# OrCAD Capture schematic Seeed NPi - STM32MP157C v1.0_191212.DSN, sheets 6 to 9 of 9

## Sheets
6 04 USB HOST/Device: size A3
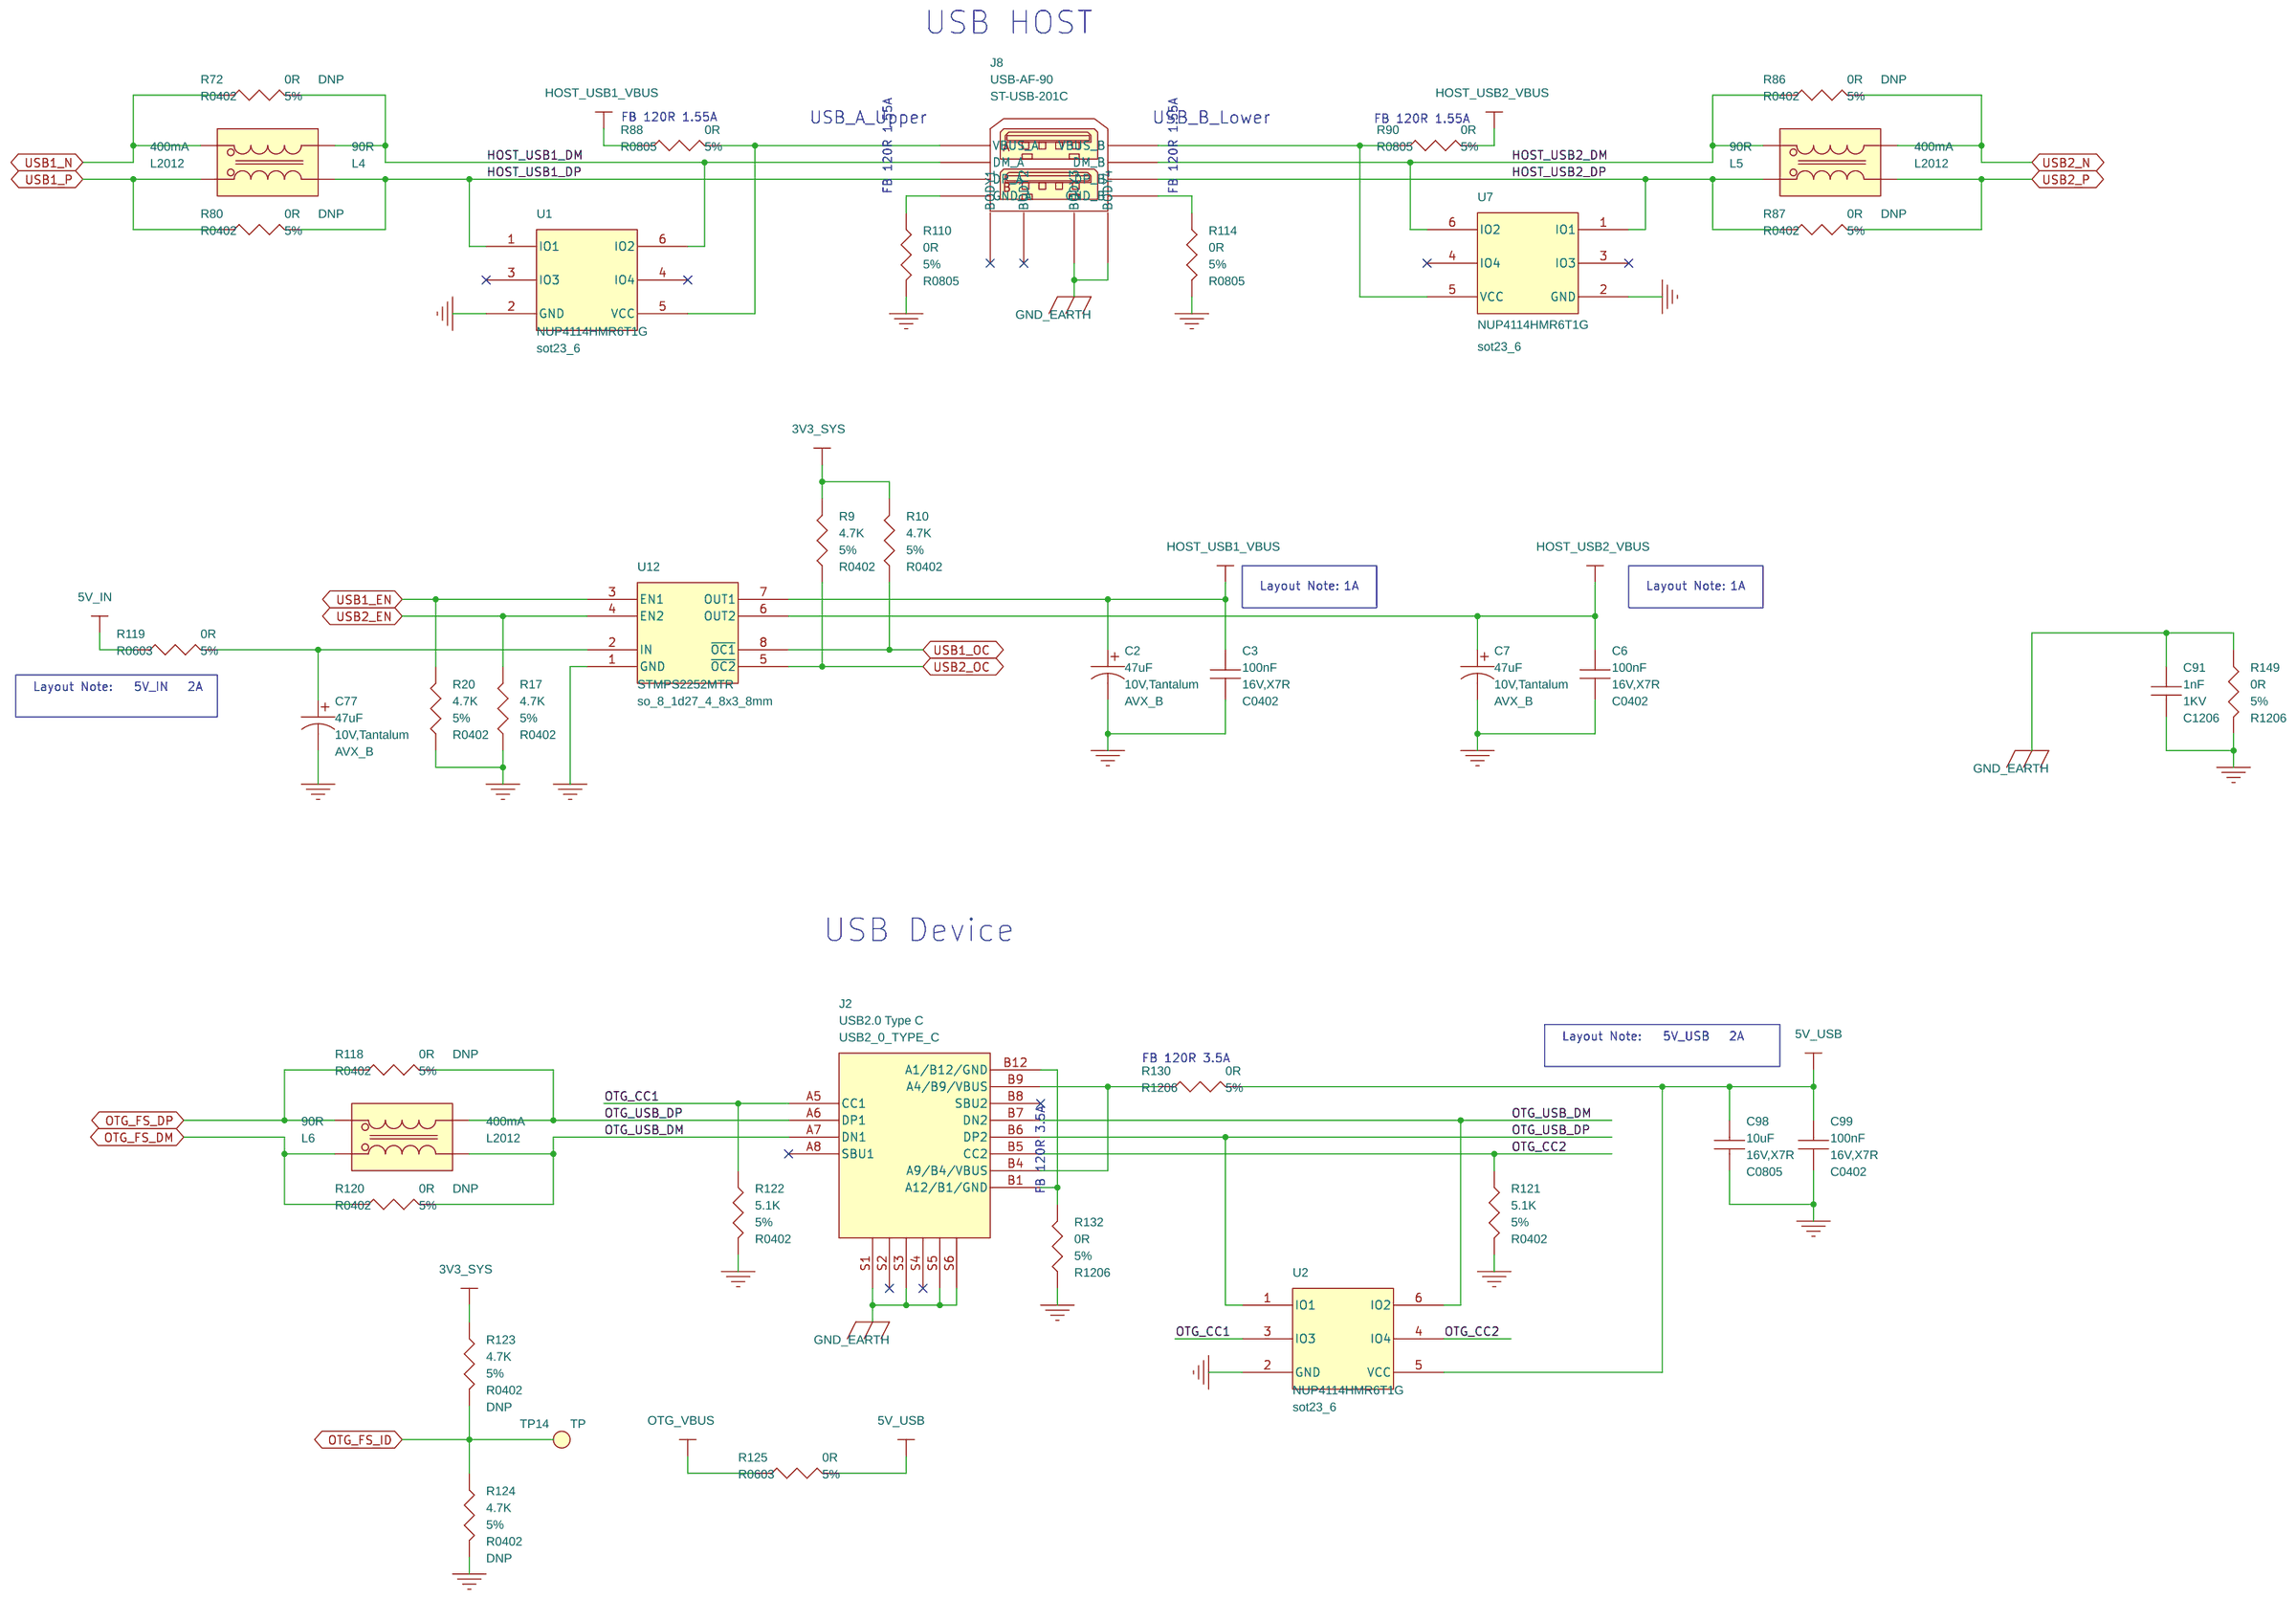
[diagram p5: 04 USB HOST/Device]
7 01 Title / Revision History
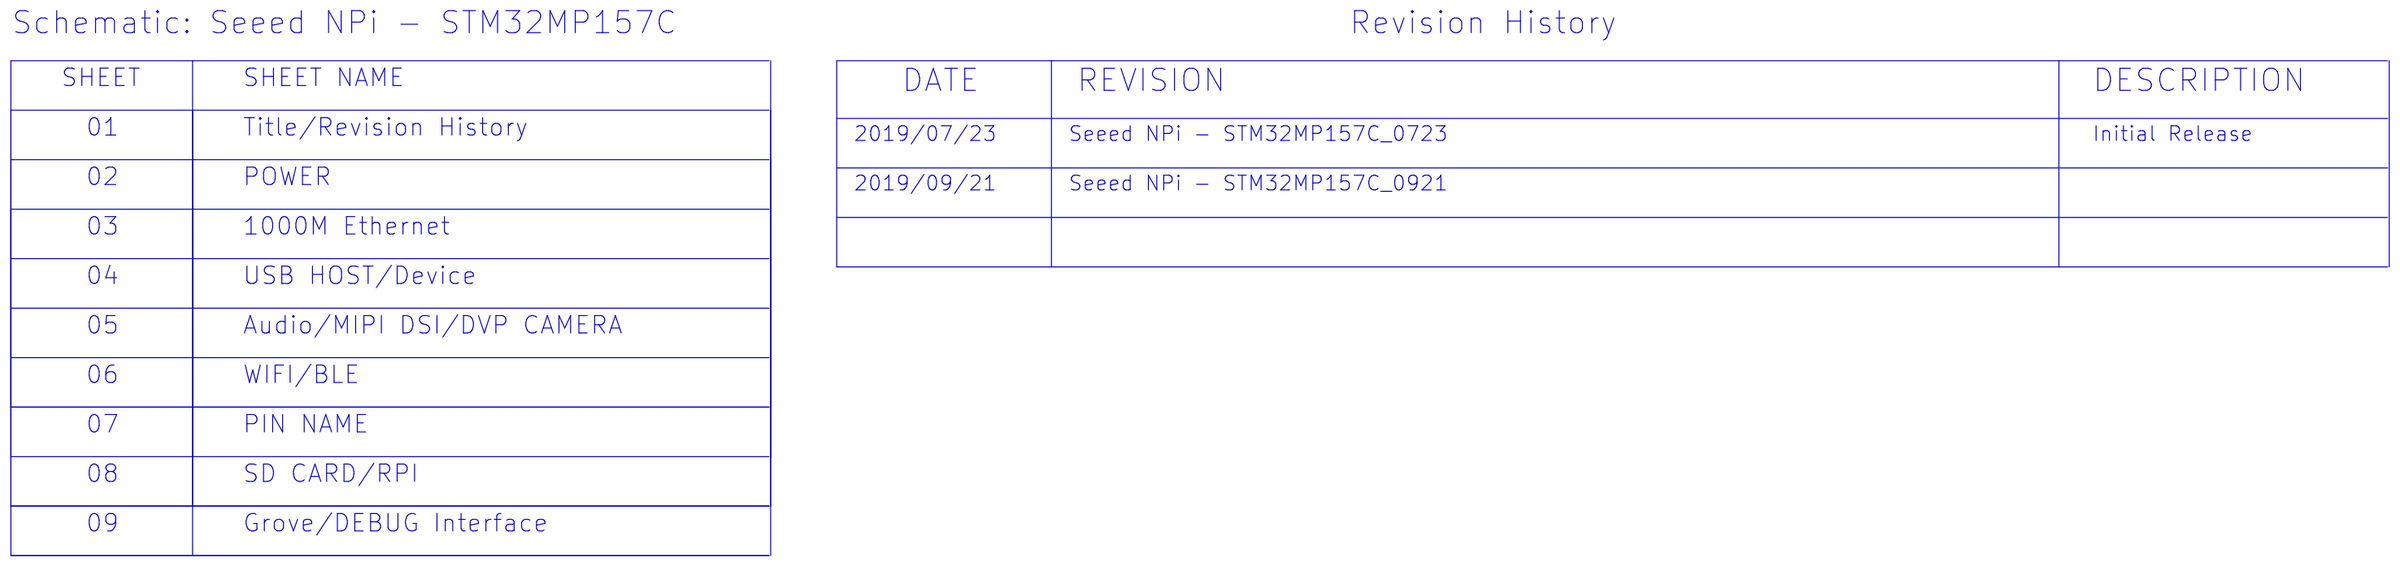
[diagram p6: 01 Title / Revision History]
8 09 Grove/DEBUG Interface: size A3
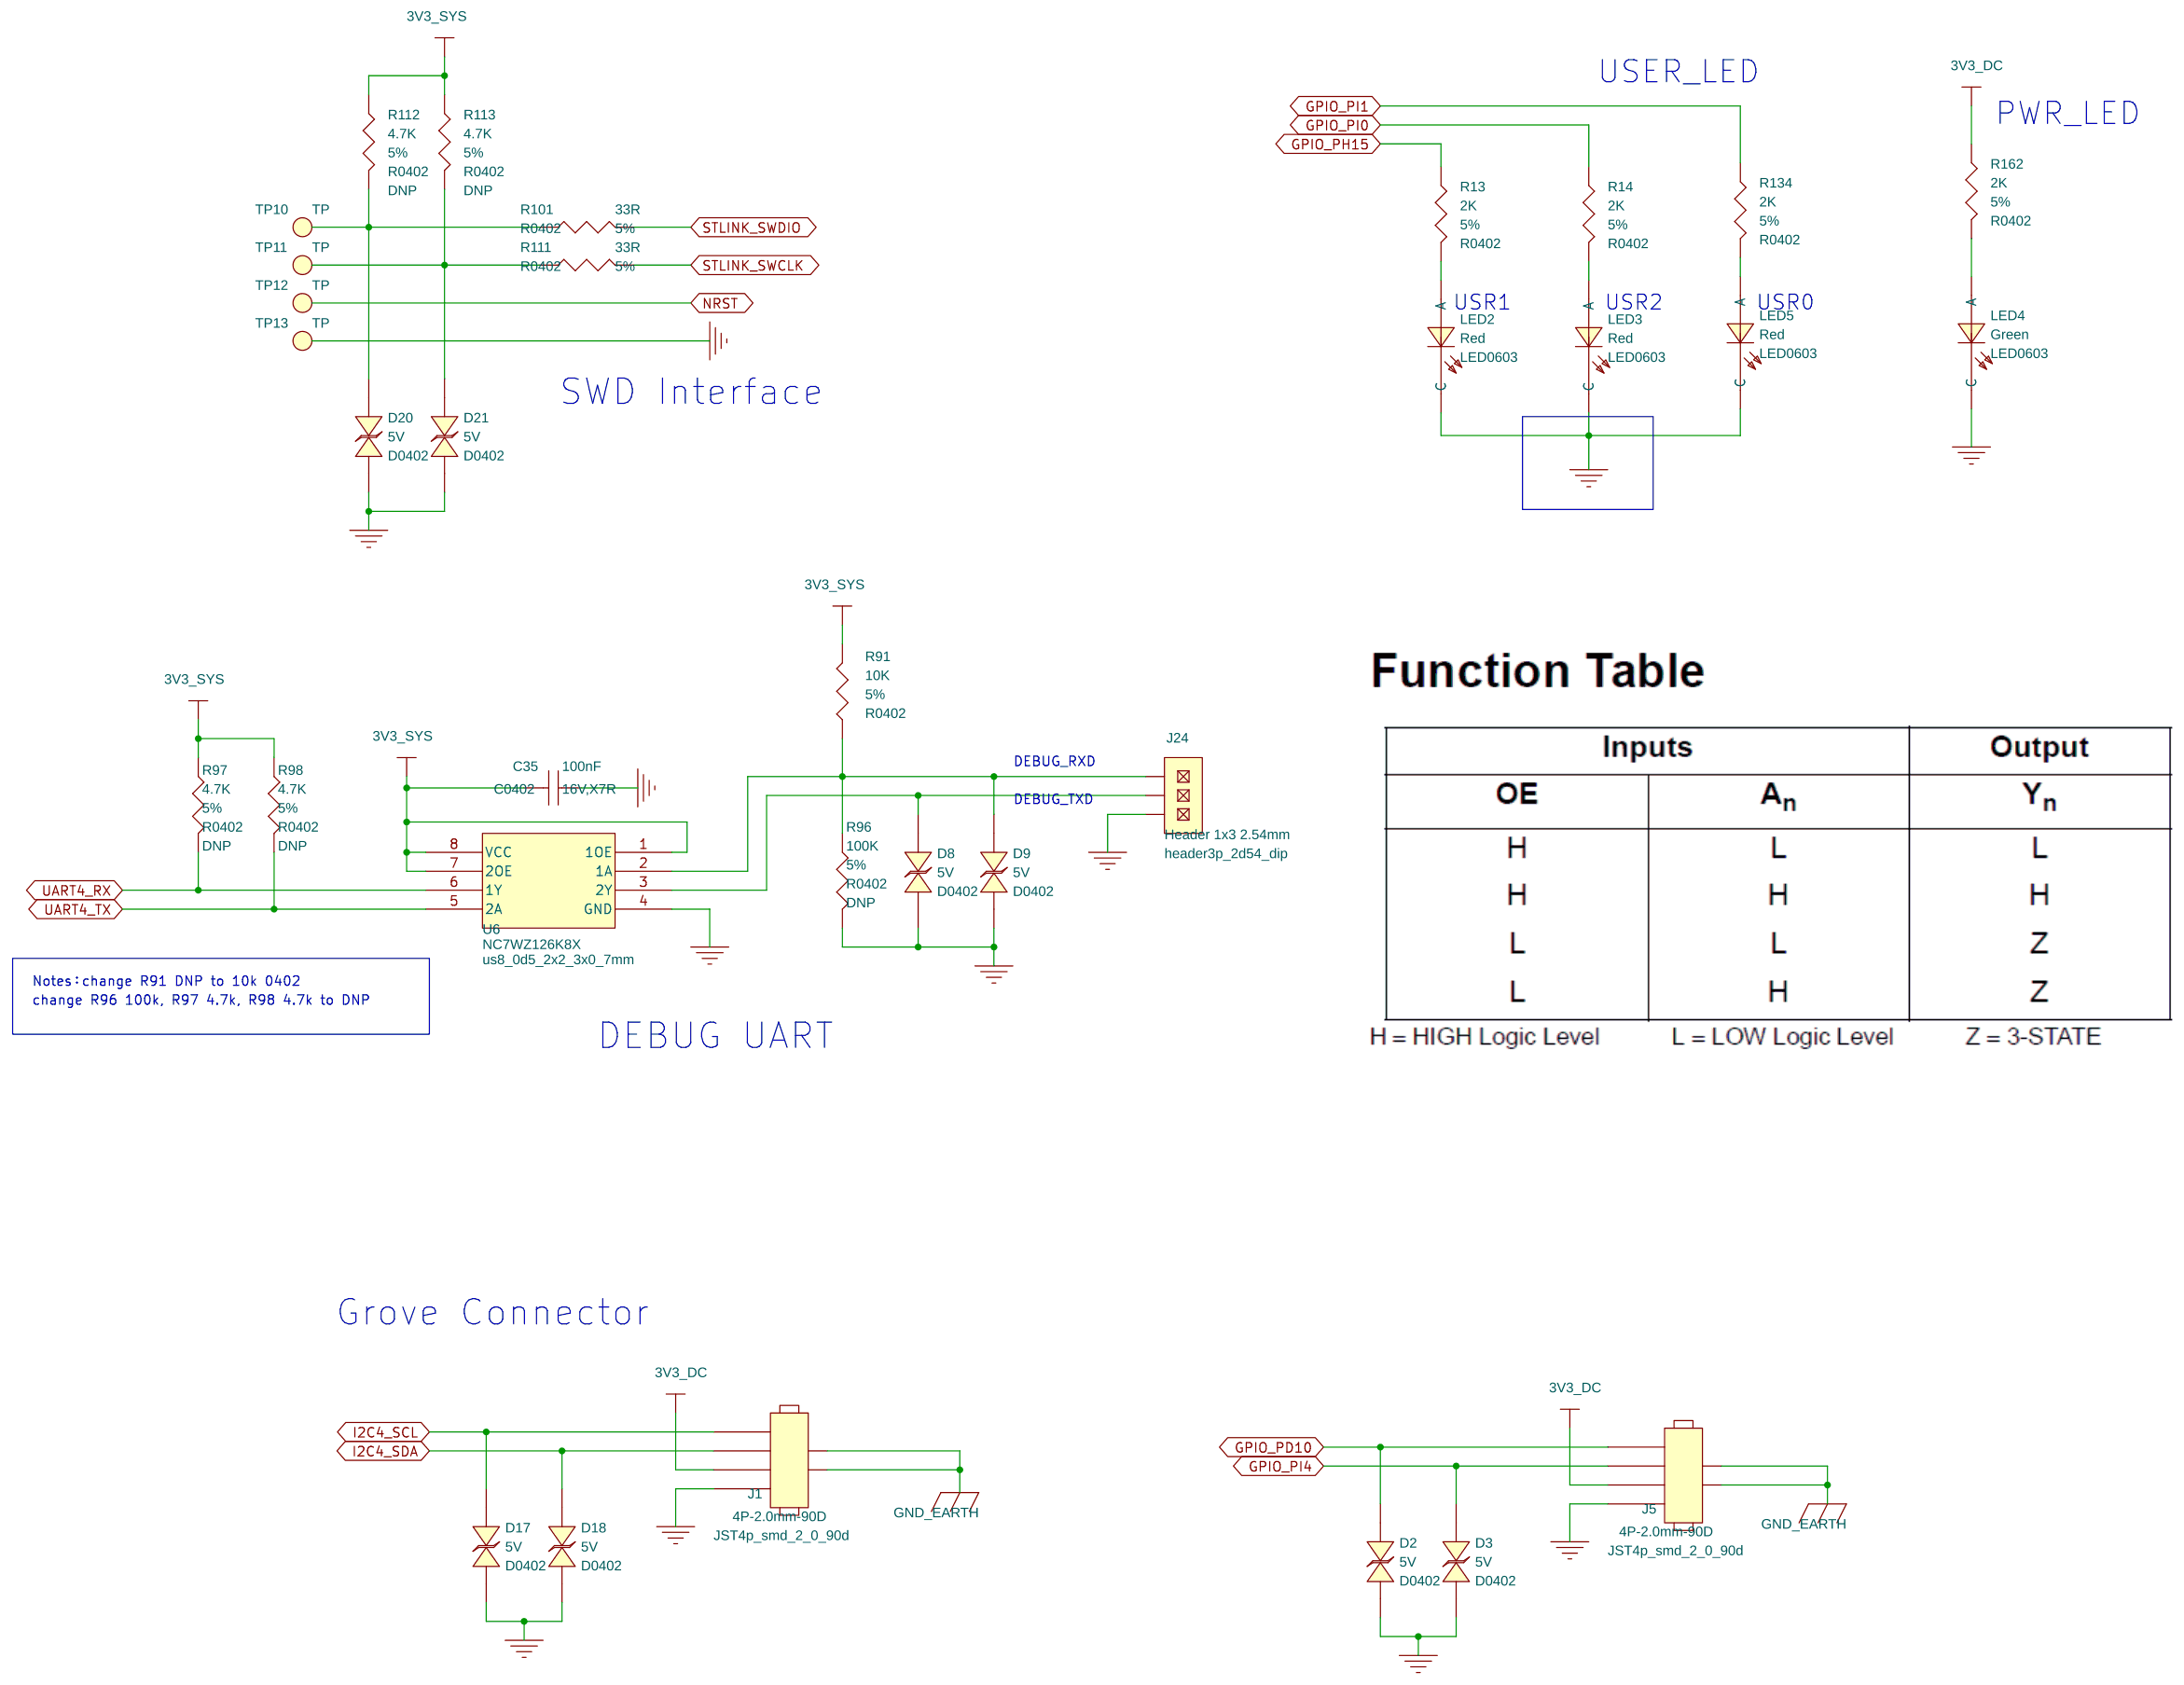
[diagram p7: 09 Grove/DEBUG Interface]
9 05 Audio/MIPI DSI/DVP CAMERA: size A3
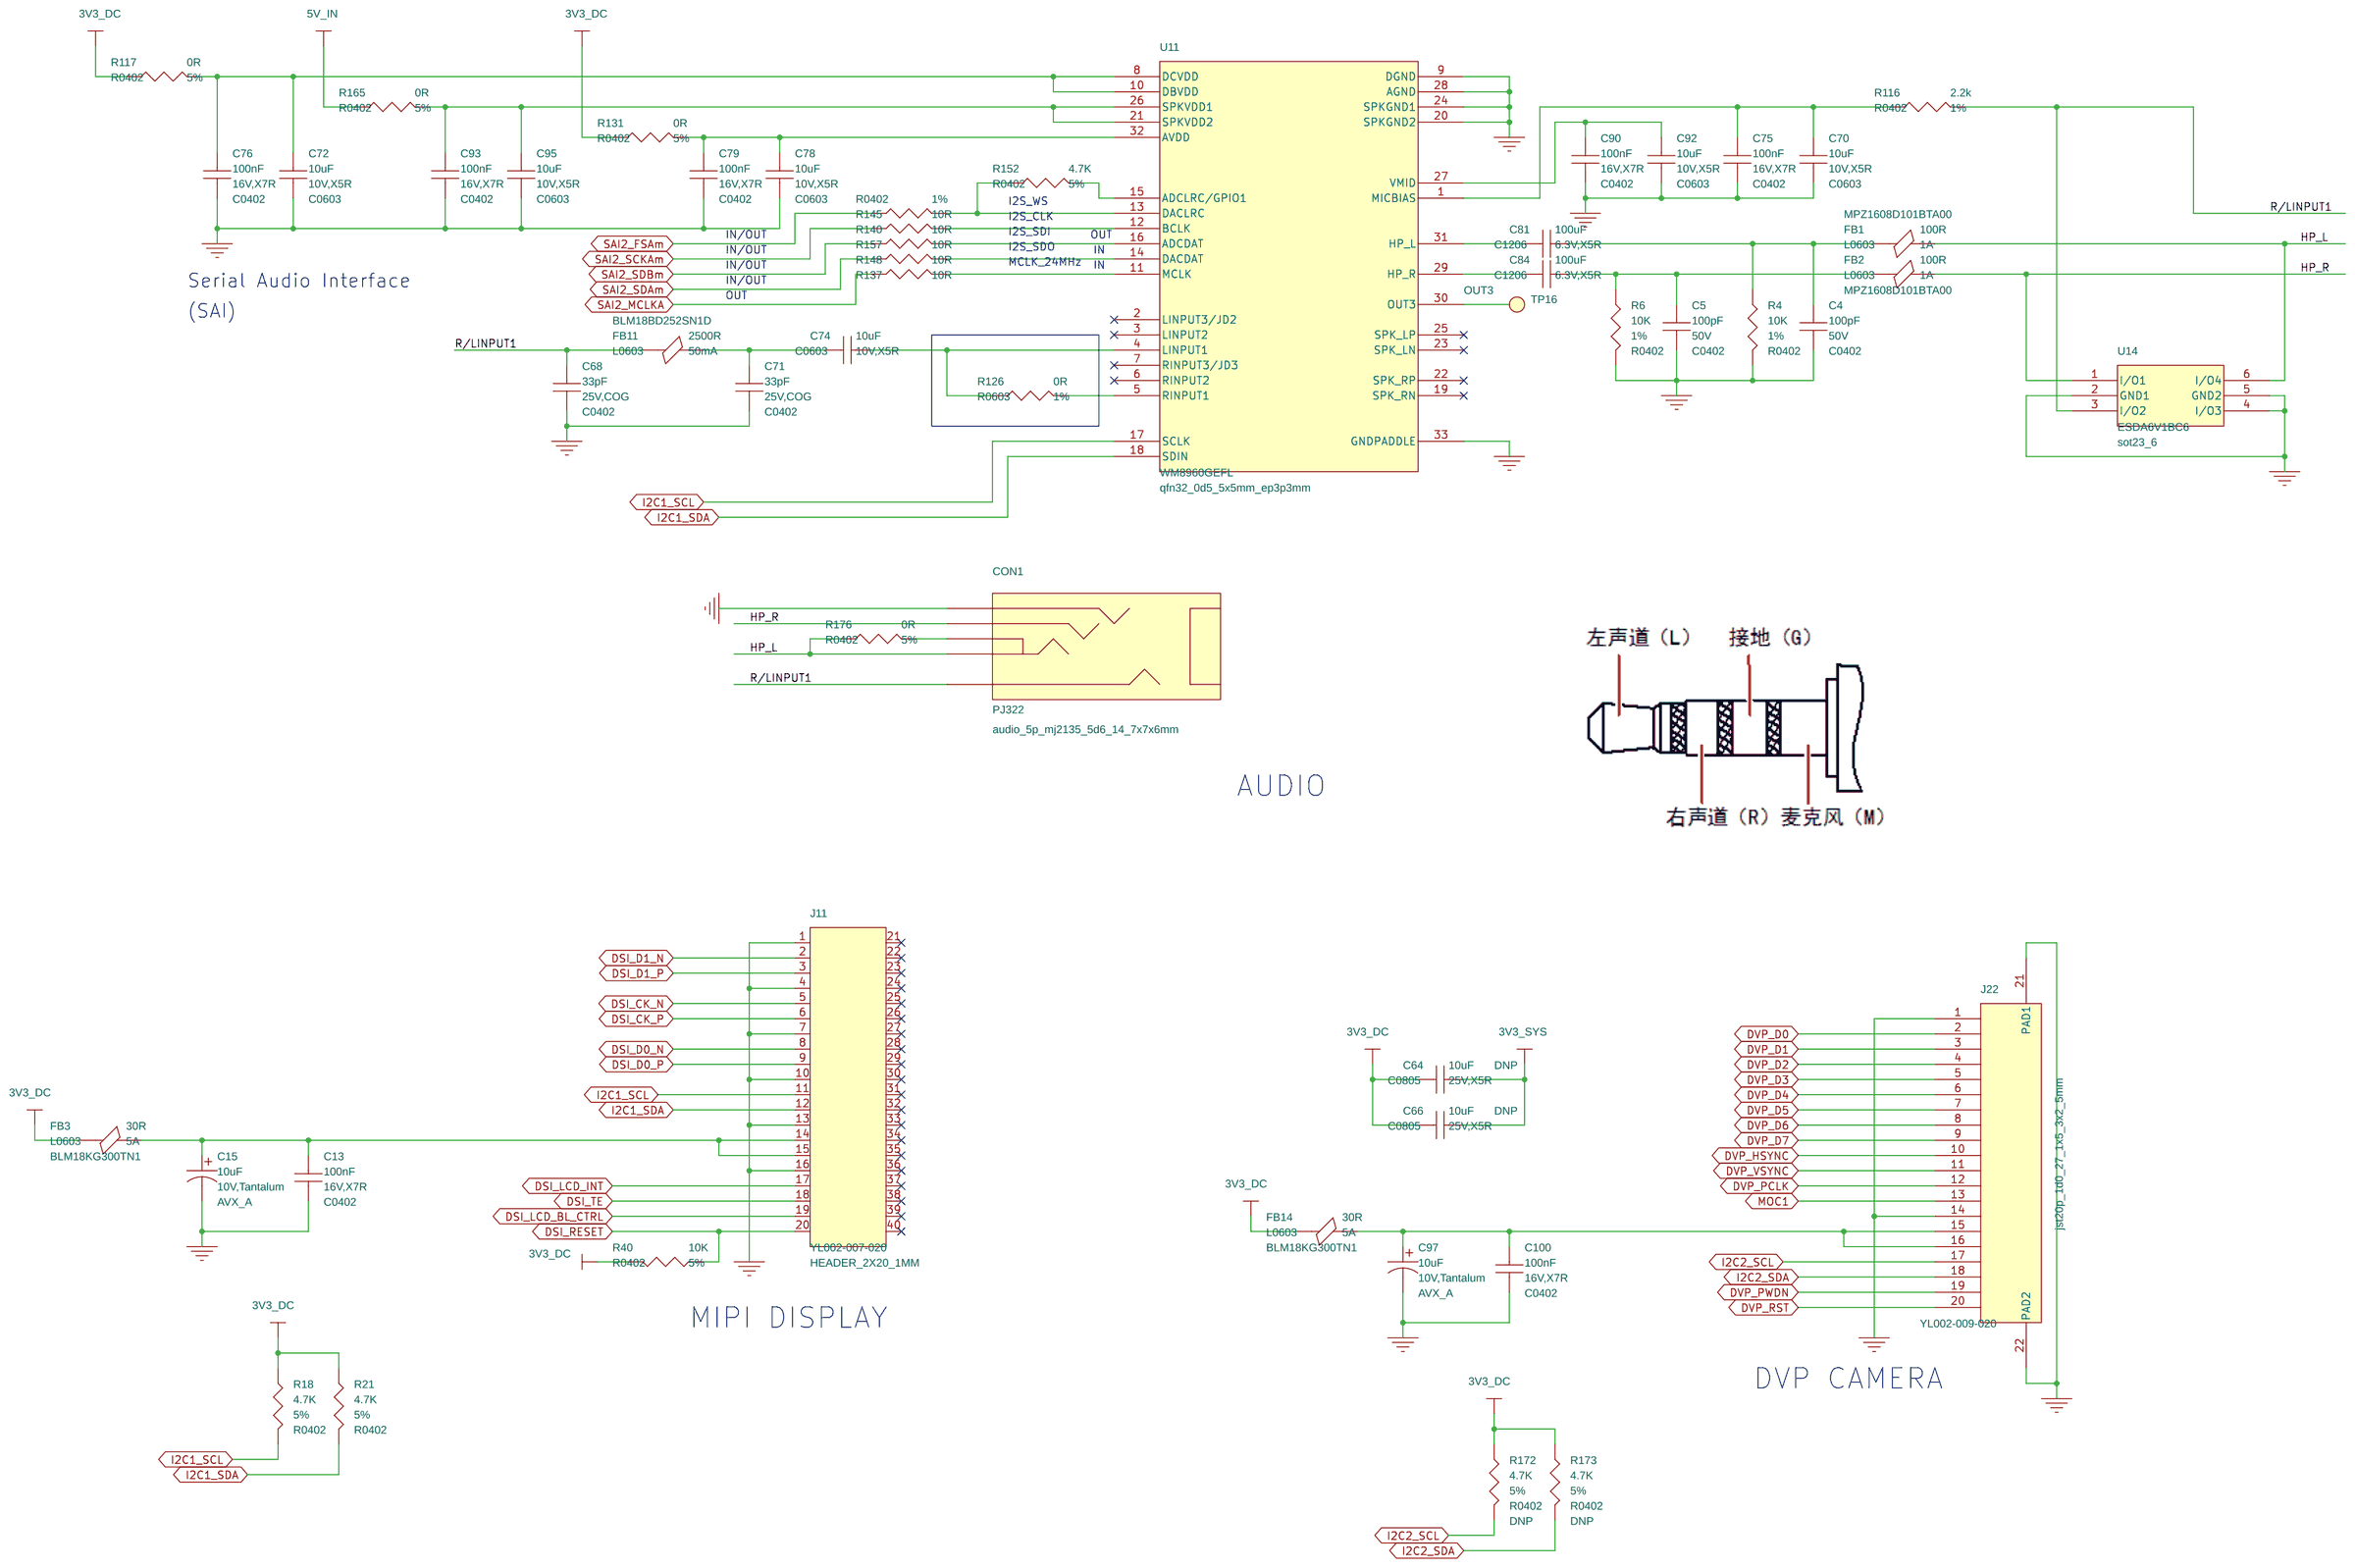
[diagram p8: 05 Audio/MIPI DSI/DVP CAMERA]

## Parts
sheet 04 USB HOST/Device
C2  47uF  [AVX_B]
C3  100nF  [C0402]
C6  100nF  [C0402]
C7  47uF  [AVX_B]
C77  47uF  [AVX_B]
C91  1nF  [C1206]
C98  10uF  [C0805]
C99  100nF  [C0402]
J2  USB2.0 Type C  [USB2_0_TYPE_C]
J8  USB-AF-90  [ST-USB-201C]
L4  90R  [L2012]
L5  90R  [L2012]
L6  90R  [L2012]
R9  4.7K  [R0402]
R10  4.7K  [R0402]
R17  4.7K  [R0402]
R20  4.7K  [R0402]
R72  0R  [R0402]
R80  0R  [R0402]
R86  0R  [R0402]
R87  0R  [R0402]
R88  0R  [R0805]
R90  0R  [R0805]
R110  0R  [R0805]
R114  0R  [R0805]
R118  0R  [R0402]
R119  0R  [R0603]
R120  0R  [R0402]
R121  5.1K  [R0402]
R122  5.1K  [R0402]
R123  4.7K  [R0402]
R124  4.7K  [R0402]
R125  0R  [R0603]
R130  0R  [R1206]
R132  0R  [R1206]
R149  0R  [R1206]
TP14  TP  [TP60C_SMD]
U1  NUP4114HMR6T1G  [sot23_6]
U2  NUP4114HMR6T1G  [sot23_6]
U7  NUP4114HMR6T1G  [sot23_6]
U12  STMPS2252MTR  [so_8_1d27_4_8x3_8mm]
sheet 05 Audio/MIPI DSI/DVP CAMERA
C4  100pF  [C0402]
C5  100pF  [C0402]
C13  100nF  [C0402]
C15  10uF  [AVX_A]
C64  10uF  [C0805]
C66  10uF  [C0805]
C68  33pF  [C0402]
C70  10uF  [C0603]
C71  33pF  [C0402]
C72  10uF  [C0603]
C74  10uF  [C0603]
C75  100nF  [C0402]
C76  100nF  [C0402]
C78  10uF  [C0603]
C79  100nF  [C0402]
C81  100uF  [C1206]
C84  100uF  [C1206]
C90  100nF  [C0402]
C92  10uF  [C0603]
C93  100nF  [C0402]
C95  10uF  [C0603]
C97  10uF  [AVX_A]
C100  100nF  [C0402]
CON1  PJ322  [audio_5p_mj2135_5d6_14_7x7x6mm]
FB1  100R  [L0603]
FB2  100R  [L0603]
FB3  30R  [L0603]
FB11  2500R  [L0603]
FB14  30R  [L0603]
J11  YL002-007-020  [HEADER_2X20_1MM]
J22  YL002-009-020  [jst20p_1d0_27_1x5_3x2_5mm]
R4  10K  [R0402]
R6  10K  [R0402]
R18  4.7K  [R0402]
R21  4.7K  [R0402]
R40  10K  [R0402]
R116  2.2k  [R0402]
R117  0R  [R0402]
R126  0R  [R0603]
R131  0R  [R0402]
R137  10R  [R0402]
R140  10R  [R0402]
R145  10R  [R0402]
R148  10R  [R0402]
R152  4.7K  [R0402]
R157  10R  [R0402]
R165  0R  [R0402]
R172  4.7K  [R0402]
R173  4.7K  [R0402]
R176  0R  [R0402]
TP16  OUT3  [TP30C_SMD]
U11  WM8960GEFL  [qfn32_0d5_5x5mm_ep3p3mm]
U14  ESDA6V1BC6  [sot23_6]
sheet 09 Grove/DEBUG Interface
C35  100nF  [C0402]
D2  ESDPSA0402V05  [D0402]
D3  ESDPSA0402V05  [D0402]
D8  ESDPSA0402V05  [D0402]
D9  ESDPSA0402V05  [D0402]
D17  ESDPSA0402V05  [D0402]
D18  ESDPSA0402V05  [D0402]
D20  ESDPSA0402V05  [D0402]
D21  ESDPSA0402V05  [D0402]
J1  4P-2.0mm-90D  [JST4p_smd_2_0_90d]
J5  4P-2.0mm-90D  [JST4p_smd_2_0_90d]
J24  Header 1x3 2.54mm  [header3p_2d54_dip]
LED2  Red  [LED0603]
LED3  Red  [LED0603]
LED4  Green  [LED0603]
LED5  Red  [LED0603]
R13  2K  [R0402]
R14  2K  [R0402]
R91  10K  [R0402]
R96  100K  [R0402]
R97  4.7K  [R0402]
R98  4.7K  [R0402]
R101  33R  [R0402]
R111  33R  [R0402]
R112  4.7K  [R0402]
R113  4.7K  [R0402]
R134  2K  [R0402]
R162  2K  [R0402]
TP10  TP  [TP60C_SMD]
TP11  TP  [TP60C_SMD]
TP12  TP  [TP60C_SMD]
TP13  TP  [TP60C_SMD]
U6  NC7WZ126K8X  [us8_0d5_2x2_3x0_7mm]

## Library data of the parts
C2 C7 C77 = CT: SMD CAP Tantalum 47uF-10V;B; Manufacturer: AVX; Manufacturer Part Number: TAJB476K010RNJ; PN: 302020020; Part Type: Tantalum; Rating: 10V,Tantalum; Status: BeagleBone Carrier Board
C3 C6 C13 C35 C75 C76 C79 C90 C93 C99 C100 = CC: SMD CAP Ceramic 100nF-16V-10%-X7R;0402; Manufacturer: YAGEO; Manufacturer Part Number: CC0402KRX7R7BB104; PN: 302010004; Part Type: Ceramic; Rating: 16V,X7R; Status: BeagleBone Carrier Board; Temperature: -55°C to 125°C
C91 = CC: SMD CAP Ceramic 1nF-1KV-10%-X7R;1206; Manufacturer: YAGEO; Manufacturer Part Number: CC1206KKX7RCBB102; PN: 302010189; Part Type: Ceramic; Rating: 1KV; Status: BeagleBone Carrier Board; Temperature: -55°C to 125°C
C98 = CC: SMD CAP Ceramic 10uF-16V-10%-X7R;0805; Manufacturer: YAGEO; Manufacturer Part Number: CC0805MKX7R7BB106; PN: 302011546; Part Type: Ceramic; Rating: 16V,X7R; Status: Sensecap Gateway V1; Temperature: -55°C to 125°C
J2 = USB2.0_Type_C_16+6P: SMD USB Type C;(16P+4)-L8.94*W7.55mm; Manufacturer: 商祺电子; Manufacturer Part Number: ST-USB-3316; PN: 320010698; Part Type: USB; Status: Grove AI HAT for Edge Computing
J8 = Dual_USB_A: DIP USB FEMAL TYPE A;8P-2.0-90D; Manufacturer: 宇亮; PN: 320010475; Part Type: USB; Status: BeagleBone Carrier Board
L4-L6 = CL: SMD Common Mode Filter 90R-400mA;4P-L2.0*W1.2*H1.4m; Manufacturer: Bourns; Manufacturer Part Number: SRF2012-900YA; PN: 303050063; Part Type: Common Mode Filter; Rating: 400mA; Status: BeagleBone Carrier Board; Temperature: -40°C to 125°C
R9 R10 R17 R18 R20 R21 R152 = R: SMD RES 4.7K-5%-1/16W;0402; Manufacturer: YAGEO; Manufacturer Part Number: RC0402JR-074K7L; PN: 301010010; Part Type: RES; Rating: 5%; Status: BeagleBone Carrier Board; Temperature: -55°C to 155°C
R72 R80 R86 R87 R118 R120 = R: SMD RES 0R-5%-1/16W;0402; ASSY: DNP; Manufacturer: YAGEO; Manufacturer Part Number: RC0402JR-070RL; PN: 301010000; Part Type: RES; Rating: 5%; Status: BeagleBone Carrier Board; Temperature: -55°C to 155°C
R88 R90 R110 R114 = R: SMD RES 0R-5%-1/8W;0805; Manufacturer: YAGEO; Manufacturer Part Number: RC0805JR-070RL; PN: 301010359; Part Type: RES; Rating: 5%; Status: Sensecap Gateway V1; Temperature: -55°C to 155°C
R119 R125 = R: SMD RES 0R-5%-1/10W;0603; Manufacturer: YAGEO; Manufacturer Part Number: RC0603JR-070RL; PN: 301010292; Part Type: RES; Rating: 5%; Temperature: -55°C to 155°C
R121 R122 = R: SMD RES 5.1K-5%-1/16W;0402; Manufacturer: YAGEO; Manufacturer Part Number: RC0402JR-075K1L; PN: 301010017; Part Type: RES; Rating: 5%; Status: Grove AI HAT for Edge Computing; Temperature: -55°C to 155°C
R97 R98 R112 R113 R123 R124 R172 R173 = R: SMD RES 4.7K-5%-1/16W;0402; ASSY: DNP; Manufacturer: YAGEO; Manufacturer Part Number: RC0402JR-074K7L; PN: 301010010; Part Type: RES; Rating: 5%; Status: BeagleBone Carrier Board; Temperature: -55°C to 155°C
R130 R132 R149 = R: SMD RES 0R-5%-1/4W;1206; Manufacturer: YAGEO; Manufacturer Part Number: RC1206JR-070RL; PN: 301010407; Part Type: RES; Rating: 5%; Status: BeagleBone Carrier Board; Temperature: -55°C to 155°C
TP10-TP14 TP16 = TESTPT1
U1 U2 U7 = NUP4114: SMD Diode ESD 5V;TSOP-6; Manufacturer: ON; PN: 304060274; Part Type: ESD; Status: ST
U12 = STMPS2252MTR: SMD IC Power Switch;8-SOIC; Manufacturer: ST; PN: 310990697; Part Type: Power Switch; Status: ST; Temperature: -40°C to 85°C
C4 C5 = CC: SMD CAP Ceramic 100pF-50V-5%-NPO;0402; Manufacturer: YAGEO; Manufacturer Part Number: CC0402JRNPO9BN101; PN: 302010012; Part Type: Ceramic; Rating: 50V; Status: Testo PoE; Temperature: -55°C to 125°C
C15 C97 = CT: SMD CAP Tantalum 10uF-10V;A; Manufacturer: AVX; Manufacturer Part Number: TAJA106K010RNJ; PN: 302020011; Part Type: Tantalum; Rating: 10V,Tantalum; Status: ST
C64 C66 = CC: SMD CAP Ceramic 10uF-25V-10%-X5R;0805; ASSY: DNP; Manufacturer: YAGEO; Manufacturer Part Number: CC0805KKX5R8BB106; PN: 302010178; Part Type: Ceramic; Rating: 25V,X5R; Status: BeagleBone Carrier Board; Temperature: -55°C to 85°C
C68 C71 = CC: SMD CAP Ceramic;33pF-25V-5%-C0G(NP0)0402; Manufacturer: Murata; Manufacturer Part Number: GRM1555C1E330JA01D; PN: 302010297; Part Type: Ceramic; Rating: 25V,COG; Status: Combox Pro; Temperature: -55°C to 125°C
C70 C72 C74 C78 C92 C95 = CC: SMD CAP Ceramic 10uF-10V-10%-X5R;0603; Manufacturer: YAGEO; Manufacturer Part Number: CC0603KRX5R6BB106; PN: 302010103; Part Type: Ceramic; Rating: 10V,X5R; Status: BeagleBone Carrier Board; Temperature: -55°C to 85°C
C81 C84 = CC: SMD CAP Ceramic 100uF-6.3V-20%-X5R;1206; Manufacturer: YAGEO; Manufacturer Part Number: CC1206MKX5R5BB107; PN: 302010742; Part Type: Ceramic; Rating: 6.3V,X5R; Status: BeagleBone Carrier Board; Temperature: -55°C to 85°C
CON1 = Earphone_Jack: DIP Audio Jack;Black-5P-15*7*6mm; Manufacturer: 德艺隆; PN: 320040282; Part Type: Earphone Jack; Status: Eagleye 310s
FB1 FB2 = FB: SMD Ferrite Bead 100R-1A;0603; Manufacturer: TDK; Manufacturer Part Number: MPZ1608D101BTA00; PN: 303030139; Part Type: Ferrite Bead; Rating: 1A; Status: ST; Temperature: -55°C to 125°C
FB3 FB14 = FB: SMD Ferrite Bead 30R-5A;0603; Manufacturer: Murata; Manufacturer Part Number: BLM18KG300TN1; PN: 303030421; Part Type: Ferrite Bead; Rating: 5A; Status: ST
FB11 = FB: SMD Ferrite Bead 2500R-50mA;0603; Manufacturer: Murata; Manufacturer Part Number: BLM18BD252SN1D; PN: 303030020; Part Type: Ferrite Bead; Rating: 50mA; Status: ST; Temperature: -55°C to 125°C
J11 = Header_2x20_Of_ST: SMD FPC CONN;2*20P-1mm-90D; Manufacturer: 宇亮; PN: 320060504; Part Type: FPC Connectors; Status: ST
J22 = Header_20+2P: SMD FPC CONN;20P-1mm; Manufacturer: 宇亮; PN: 320060524; Part Type: FPC Connectors; Status: ST; Temperature: -20°C to 85°C
R4 R6 = R: SMD RES 10K-1%-1/16W;0402; Manufacturer: YAGEO; Manufacturer Part Number: RC0402FR-0710KL; PN: 301010047; Part Type: RES; Rating: 1%; Status: BeagleBone Carrier Board; Temperature: -55°C to 155°C
R40 R91 = R: SMD RES 10K-5%-1/16W;0402; Manufacturer: YAGEO; Manufacturer Part Number: RC0402JR-0710KL; PN: 301010004; Part Type: RES; Rating: 5%; Status: BeagleBone Carrier Board; Temperature: -55°C to 155°C
R116 = R: SMD RES 2.2K-1%-1/16W;0402; Manufacturer: YAGEO; Manufacturer Part Number: RC0402FR-072K2L; PN: 301010746; Part Type: RES; Rating: 1%; Status: ST; Temperature: -55°C to 155°C
R117 R131 R165 R176 = R: SMD RES 0R-5%-1/16W;0402; Manufacturer: YAGEO; Manufacturer Part Number: RC0402JR-070RL; PN: 301010000; Part Type: RES; Rating: 5%; Status: BeagleBone Carrier Board; Temperature: -55°C to 155°C
R126 = R: SMD RES 0R-1%-1/10W;0603; Manufacturer: YAGEO; Manufacturer Part Number: RC0603FR-070RL; PN: 301012029; Part Type: RES; Rating: 1%; Status: BBG Gateway; Temperature: -55°C to 155°C
R137 R140 R145 R148 R157 = R: SMD RES 10R-1%-1/16W;0402; Manufacturer: YAGEO; Manufacturer Part Number: RC0402FR-0710RL; PN: 301010444; Part Type: RES; Rating: 1%; Status: IOT Enabling Dongle Board; Temperature: -55°C to 155°C
U11 = WM8960: SMD IC Codecoder;QFN-32; Manufacturer: Wolfson; PN: 310080009; Part Type: Codec; Status: ST; Temperature: -40℃ to 85℃
U14 = ESDA6V1BC6: SMD Diode ESD 5V;SOT-23-6; Manufacturer: ST; PN: 304060235; Part Type: ESD; Status: ST; Temperature: -40°C to 125°C
D2 D3 D8 D9 D17 D18 D20 D21 = DIODE_TVS_BI-DIR: SMD Diode ESD 0.05pF;0402; Manufacturer: SEMITEL; PN: 304060074; Part Type: TVS; Rating: 5V; Status: BeagleBone Carrier Board; Temperature: -40°C to 90°C
J1 J5 = Header_4+2P: SMD Grove Female Header-Beige;4P-2.0-90D; Manufacturer: 西格益; Manufacturer Part Number: HY2.0-A 90D SMD; PN: 320110032; Part Type: Header; Status: Eagleye 310s
J24 = Header_1x3: DIP Black Male Header VERT;1*3P-2.54-2.54-11.6/3.0mm; Manufacturer: 宇熙; Manufacturer Part Number: P125-1103A1BS116A1; PN: 320020079; Part Type: Header; Status: ST; Temperature: -20°C to 105°C
LED2 LED3 LED5 = Single_LED: SMD LED Clear-Red;LED-0603; Manufacturer: Everlight; Manufacturer Part Number: EL-19-217/R6C-AL1M2VY/3T; PN: 304090042; Part Type: LED; Status: BeagleBone Carrier Board
LED4 = Single_LED: SMD LED Clear-Green;LED-0603; Manufacturer: Everlight; Manufacturer Part Number: 19-217/G7C-AN1P2/3T; PN: 304090043; Part Type: LED; Status: BeagleBone Carrier Board; Temperature: -40°C to 85°C
R13 R14 R134 R162 = R: SMD RES 2K-5%-1/16W;0402; Manufacturer: YAGEO; Manufacturer Part Number: RC0402JR-072KL; PN: 301010065; Part Type: RES; Rating: 5%; Status: Grove AI HAT for Edge Computing; Temperature: -55°C to 155°C
R96 = R: SMD RES 100K-5%-1/16W;0402; ASSY: DNP; Manufacturer: YAGEO; Manufacturer Part Number: RC0402JR-07100KL; PN: 301010033; Part Type: RES; Rating: 5%; Status: BeagleBone Carrier Board; Temperature: -55°C to 155°C
R101 R111 = R: SMD RES 33R-5%-1/16W;0402; Manufacturer: YAGEO; Manufacturer Part Number: RC0402JR-0733RL; PN: 301010034; Part Type: RES; Rating: 5%; Status: BeagleBone Carrier Board; Temperature: -55°C to 155°C
U6 = NC7WZ126: SMD IC Logic;8-VFSOP; Manufacturer: ON; PN: 310050870; Part Type: Buffer; Status: ST; Temperature: -40°C to 85°C

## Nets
3V3_DC: C64.1 C66.1 FB3.1 FB14.1 J1.3 J5.3 R18.1 R21.1 R40.2 R117.1 R131.1 R162.1 R172.1 R173.1 ; also on sheet 1 2 4 5
3V3_SYS: C35.2 C64.2 C66.2 R9.2 R10.2 R91.2 R97.1 R98.1 R112.1 R113.1 R123.1 U6.1(1OE) U6.7(2OE) U6.8(VCC) ; also on sheet 2 3 4 5
5V_IN: R119.1 R165.1 ; also on sheet 2 3 4
5V_USB: C98.1 C99.1 R125.2 R130.2 U2.5(VCC) ; also on sheet 2
GND: C2.2 C3.2 C4.2 C5.2 C6.2 C7.2 C13.2 C15.2 C35.1 C68.2 C70.2 C71.2 C72.2 C75.2 C76.2 C77.2 C78.2 C79.2 C90.2 C91.2 C92.2 C93.2 C95.2 C97.2 C98.2 C99.2 C100.2 CON1.2 D2.2 D3.2 D8.2 D9.2 D17.2 D18.2 D20.2 D21.2 J1.4 J5.4 J11.1 J11.4 J11.7 J11.10 J11.13 J11.16 J22.1 J22.14 J22.21(PAD1) J22.22(PAD2) J24.3 LED2.2(C) LED3.2(C) LED4.2(C) LED5.2(C) R4.2 R6.2 R17.1 R20.1 R96.2 R110.2 R114.2 R121.2 R122.2 R124.2 R132.1 R149.2 TP13.1(TP) U1.2(GND) U2.2(GND) U6.4(GND) U7.2(GND) U11.9(DGND) U11.20(SPKGND2) U11.24(SPKGND1) U11.28(AGND) U11.33(GNDPADDLE) U12.1(GND) U14.2(GND1) U14.4(I/O3) U14.5(GND2) ; also on sheet 1 2 3 4 5
GND_EARTH: C91.1 J1.5 J1.6 J2.S1 J2.S3 J2.S5 J2.S6 J5.5 J5.6 J8.S3(BODY3) J8.S4(BODY4) R149.1 ; also on sheet 1 3 4
DSI_CK_N: J11.5 ; also on sheet 3
DSI_CK_P: J11.6 ; also on sheet 3
DSI_D0_N: J11.8 ; also on sheet 3
DSI_D0_P: J11.9 ; also on sheet 3
DSI_D1_N: J11.2 ; also on sheet 3
DSI_D1_P: J11.3 ; also on sheet 3
DSI_LCD_BL_CTRL: J11.19 ; also on sheet 3
DSI_LCD_INT: J11.17 ; also on sheet 3
DSI_RESET: J11.20 R40.1 ; also on sheet 3
DSI_TE: J11.18 ; also on sheet 3
DVP_D0: J22.2 ; also on sheet 3
DVP_D1: J22.3 ; also on sheet 3
DVP_D2: J22.4 ; also on sheet 3
DVP_D3: J22.5 ; also on sheet 3
DVP_D4: J22.6 ; also on sheet 3
DVP_D5: J22.7 ; also on sheet 3
DVP_D6: J22.8 ; also on sheet 3
DVP_D7: J22.9 ; also on sheet 3
DVP_HSYNC: J22.10 ; also on sheet 3
DVP_PCLK: J22.12 ; also on sheet 3
DVP_PWDN: J22.19 ; also on sheet 3
DVP_RST: J22.20 ; also on sheet 3
DVP_VSYNC: J22.11 ; also on sheet 3
GPIO_PD10: D2.1 J5.1 ; also on sheet 3
GPIO_PH15: R13.1 ; also on sheet 3
GPIO_PI0: R14.1 ; also on sheet 3
GPIO_PI1: R134.1 ; also on sheet 3
GPIO_PI4: D3.1 J5.2 ; also on sheet 3
HOST_USB1_DM: J8.A2(DM_A) L4.2 R72.2 U1.6(IO2)
HOST_USB1_DP: J8.A3(DP_A) L4.3 R80.2 U1.1(IO1)
HOST_USB1_VBUS: C2.1 C3.1 R88.1 U12.7(OUT1)
HOST_USB2_DM: J8.B2(DM_B) L5.1 R86.1 U7.6(IO2)
HOST_USB2_DP: J8.B3(DP_B) L5.4 R87.1 U7.1(IO1)
HOST_USB2_VBUS: C6.1 C7.1 R90.2 U12.6(OUT2)
HP_L: CON1.5 FB1.2 R176.1 U14.6(I/O4)
HP_R: CON1.3 FB2.2 U14.1(I/O1)
I2C1_SCL: J11.11 R18.2 U11.17(SCLK) ; also on sheet 3 4
I2C1_SDA: J11.12 R21.2 U11.18(SDIN) ; also on sheet 3 4
I2C2_SCL: J22.17 R172.2 ; also on sheet 3
I2C2_SDA: J22.18 R173.2 ; also on sheet 3
I2C4_SCL: D17.1 J1.1 ; also on sheet 3 4
I2C4_SDA: D18.1 J1.2 ; also on sheet 3 4
MOC1: J22.13 ; also on sheet 3
NRST: TP12.1(TP) ; also on sheet 1 3 4
OTG_CC1: J2.A5(CC1) R122.1 U2.3(IO3)
OTG_CC2: J2.B5(CC2) R121.1 U2.4(IO4)
OTG_FS_DM: L6.4 R120.1 ; also on sheet 3
OTG_FS_DP: L6.1 R118.1 ; also on sheet 3
OTG_FS_ID: R123.2 R124.1 TP14.1(TP) ; also on sheet 3
OTG_USB_DM: J2.A7(DN1) J2.B7(DN2) L6.3 R120.2 U2.6(IO2)
OTG_USB_DP: J2.A6(DP1) J2.B6(DP2) L6.2 R118.2 U2.1(IO1)
OTG_VBUS: R125.1 ; also on sheet 3
R/LINPUT1: C68.1 CON1.1 FB11.1 R116.2 U14.3(I/O2)
SAI2_FSAm: R145.1 ; also on sheet 3
SAI2_MCLKA: R137.1 ; also on sheet 3
SAI2_SCKAm: R140.1 ; also on sheet 3
SAI2_SDAm: R148.1 ; also on sheet 3
SAI2_SDBm: R157.1 ; also on sheet 3
STLINK_SWCLK: R111.2 ; also on sheet 3
STLINK_SWDIO: R101.2 ; also on sheet 3
UART4_RX: R97.2 U6.6(1Y) ; also on sheet 3
UART4_TX: R98.2 U6.5(2A) ; also on sheet 3
USB1_EN: R20.2 U12.3(EN1) ; also on sheet 3
USB1_N: L4.1 R72.1 ; also on sheet 3
USB1_OC: R10.1 U12.8(~{OC1}) ; also on sheet 3
USB1_P: L4.4 R80.1 ; also on sheet 3
USB2_EN: R17.2 U12.4(EN2) ; also on sheet 3
USB2_N: L5.2 R86.2 ; also on sheet 3
USB2_OC: R9.1 U12.5(~{OC2}) ; also on sheet 3
USB2_P: L5.3 R87.2 ; also on sheet 3
N3835690: J8.A4(GND_A) R110.1
N3835694: J8.B4(GND_B) R114.1
N3839488: C77.1 R119.2 U12.2(IN)
N3854640: C13.1 C15.1 FB3.2 J11.14 J11.15
N3854714: C97.1 C100.1 FB14.2 J22.15 J22.16
N3873950: J2.B1(A12/B1/GND) J2.B12(A1/B12/GND) R132.2
N3874122: J2.B4(A9/B4/VBUS) J2.B9(A4/B9/VBUS) R130.1
N3931666: CON1.4 R176.2
N4046258: C74.2 R126.1 U11.4(LINPUT1)
N4046262: C78.1 C79.1 R131.2 U11.32(AVDD)
N4046268: C72.1 C76.1 R117.2 U11.8(DCVDD) U11.10(DBVDD)
N4046299: C93.1 C95.1 R165.2 U11.21(SPKVDD2) U11.26(SPKVDD1)
N4056572: R145.2 R152.1 U11.13(DACLRC)
N4056576: R140.2 U11.12(BCLK)
N4056580: R157.2 U11.16(ADCDAT)
N4056584: R148.2 U11.14(DACDAT)
N4056588: R137.2 U11.11(MCLK)
N4058145: R152.2 U11.15(ADCLRC/GPIO1)
N4058376: C90.1 C92.1 U11.27(VMID)
N4058385: C70.1 C75.1 R116.1 U11.1(MICBIAS)
N4059055: TP16.1(TP) U11.30(OUT3)
N4059075: C81.1 U11.31(HP_L)
N4059079: C84.1 U11.29(HP_R)
N4059170: C4.1 C81.2 FB1.1 R4.1
N4059174: C5.1 C84.2 FB2.1 R6.1
N4060621: C71.1 C74.1 FB11.2
N4439955: D9.1 J24.1 R91.1 R96.1 U6.2(1A)
N4439995: D8.1 J24.2 U6.3(2Y)
N4458088: D20.1 R101.1 R112.2 TP10.1(TP)
N4458139: D21.1 R111.1 R113.2 TP11.1(TP)
N4473305: J8.A1(VBUS_A) R88.2 U1.5(VCC)
N4473534: J8.B1(VBUS_B) R90.1 U7.5(VCC)
N4505708: R126.2 U11.5(RINPUT1)
N4588094: LED2.1(A) R13.2
N4589189: LED3.1(A) R14.2
N4589271: LED5.1(A) R134.2
N4607134: LED4.1(A) R162.2

Not connected (* = marked no-connect by the designer): J2 A8(SBU1)* B8(SBU2)* S2* S4*; J8 S1(BODY1)* S2(BODY2)*; J11 21* 22* 23* 24* 25* 26* 27* 28* 29* 30* 31* 32* 33* 34* 35* 36* 37* 38* 39* 40*; U1 3(IO3)* 4(IO4)*; U7 3(IO3)* 4(IO4)*; U11 2(LINPUT3/JD2)* 3(LINPUT2)* 6(RINPUT2)* 7(RINPUT3/JD3)* 19(SPK_RN)* 22(SPK_RP)* 23(SPK_LN)* 25(SPK_LP)*

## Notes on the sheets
sheet 6
- USB HOST
- FB 120R 1.55A
- USB_A_Upper
- USB_B_Lower
- FB 120R 1.55A
- FB 120R 1.55A
- FB 120R 1.55A
- Layout Note:
- 1A
- Layout Note:
- 1A
- Layout Note:
- 5V_IN   2A
- USB Device
- Layout Note:
- 5V_USB   2A
- FB 120R 3.5A
- FB 120R 3.5A
sheet 7
- Schematic: Seeed NPi - STM32MP157C
- Revision History
- SHEET
- SHEET NAME
- DATE
- REVISION
- DESCRIPTION
- 01
- Title/Revision History
- 2019/07/23
- Seeed NPi - STM32MP157C_0723
- Initial Release
- 02
- POWER
- 2019/09/21
- Seeed NPi - STM32MP157C_0921
- 03
- 1000M Ethernet
- 04
- USB HOST/Device
- 05
- Audio/MIPI DSI/DVP CAMERA
- 06
- WIFI/BLE
- 07
- PIN NAME
- 08
- SD CARD/RPI
- 09
- Grove/DEBUG Interface
sheet 8
- USER_LED
- PWR_LED
- USR1
- USR2
- USR0
- SWD Interface
- DEBUG_RXD
- DEBUG_TXD
- Notes：change R91 DNP to 10k 0402
- change R96 100k, R97 4.7k, R98 4.7k to DNP
- DEBUG UART
- Grove Connector
sheet 9
- I2S_WS
- I2S_CLK
- IN/OUT
- I2S_SDI
- OUT
- IN/OUT
- I2S_SDO
- MCLK_24MHz
- IN
- Serial Audio Interface
- IN/OUT
- IN/OUT
- IN
- OUT
- (SAI)
- AUDIO
- MIPI DISPLAY
- DVP CAMERA
